(* Logix 5000 project; controller R21 vendor 1 type 14 code 96 rev 21.11; software revision 21.00 *)

TASK DNP3ReportByException (periodic, rate 20 ms, priority 10, watchdog 500 ms) : DNP3Events
TASK MainTask (continuous, watchdog 500 ms) : MainProgram

MODULES
   Local : vendor 1 type 14 code 96 (ICP 0, rev 21.11)
      eth : vendor 1 type 12 code 200 (Ethernet 192.168.1.129, ICP 1, rev 5.7)
         DNPM01 : vendor 309 type 12 code 5212 (Ethernet 192.168.1.161, rev 1.3, StandardDataDriven RPI 500 ms)
END_MODULES

TYPE PLX51DNPInput :
STRUCT
   Instance : STRING;
   Status : PLX51DNPStatus;
   MasterMappedStatus : BOOL[1024];
   TransactionRate : DINT;
   Temperature : REAL;
   DNP3RxPacketCount : DINT;
   DNP3TxPacketCount : DINT;
   DNP3ChecksumErrors : DINT;
   DNP3MsgTimeout : DINT;
   AuthenticationFailures : DINT;
   SessionKeyChanges : DINT;
   TagReads : DINT;
   TagWrites : DINT;
   TagConnectionFailures : DINT;
   TagErrors : DINT;
   MasterEventBufferIndex : DINT;
END_STRUCT
END_TYPE

TYPE PLX51DNPOutput :
STRUCT
   RoutingInhibited : BOOL;
END_STRUCT
END_TYPE

TYPE PLX51DNPStatus :
STRUCT
   ReactiveTagMode : BOOL;
   ScheduledTagMode : BOOL;
   UnscheduledMode : BOOL;
   ConfigurationValid : BOOL;
   RoutingInhibited : BOOL;
   DNP3EventLogOk : BOOL;
   DNP3EventLogOverflow : BOOL;
END_STRUCT
END_TYPE

TYPE PSDNP3AnalogInput16Flag :
STRUCT
   Online : BOOL;
   Restart : BOOL;
   CommLost : BOOL;
   RemoteForced : BOOL;
   LocalForced : BOOL;
   OverRange : BOOL;
   ReferenceError : BOOL;
   Value : INT;
END_STRUCT
END_TYPE

TYPE PSDNP3AnalogInput32Flag :
STRUCT
   Online : BOOL;
   Restart : BOOL;
   CommLost : BOOL;
   RemoteForced : BOOL;
   LocalForced : BOOL;
   OverRange : BOOL;
   ReferenceError : BOOL;
   Value : DINT;
END_STRUCT
END_TYPE

TYPE PSDNP3AnalogInputRealFlag :
STRUCT
   Online : BOOL;
   Restart : BOOL;
   CommLost : BOOL;
   RemoteForced : BOOL;
   LocalForced : BOOL;
   OverRange : BOOL;
   ReferenceError : BOOL;
   Value : REAL;
END_STRUCT
END_TYPE

TYPE PSDNP3AnalogInputVar0 :
STRUCT
   Online : BOOL;
   Restart : BOOL;
   CommLost : BOOL;
   RemoteForced : BOOL;
   LocalForced : BOOL;
   OverRange : BOOL;
   ReferenceError : BOOL;
   IntValue : DINT;
   FloatValue : REAL;
END_STRUCT
END_TYPE

TYPE PSDNP3AnalogOutput16 :
STRUCT
   RequestPending : BOOL;
   Reserved : INT;
   Value : INT;
   Status : SINT;
END_STRUCT
END_TYPE

TYPE PSDNP3AnalogOutput32 :
STRUCT
   RequestPending : BOOL;
   Reserved : INT;
   Value : DINT;
   Status : SINT;
END_STRUCT
END_TYPE

TYPE PSDNP3AnalogOutputReal :
STRUCT
   RequestPending : BOOL;
   Reserved : INT;
   Value : REAL;
   Status : SINT;
END_STRUCT
END_TYPE

TYPE PSDNP3AnalogOutputStatus16Flag :
STRUCT
   Online : BOOL;
   Restart : BOOL;
   CommLost : BOOL;
   RemoteForced : BOOL;
   LocalForced : BOOL;
   OverRange : BOOL;
   ReferenceError : BOOL;
   Value : INT;
END_STRUCT
END_TYPE

TYPE PSDNP3AnalogOutputStatus32Flag :
STRUCT
   Online : BOOL;
   Restart : BOOL;
   CommLost : BOOL;
   RemoteForced : BOOL;
   LocalForced : BOOL;
   OverRange : BOOL;
   ReferenceError : BOOL;
   Value : DINT;
END_STRUCT
END_TYPE

TYPE PSDNP3AnalogOutputStatusRealFlag :
STRUCT
   Online : BOOL;
   Restart : BOOL;
   CommLost : BOOL;
   RemoteForced : BOOL;
   LocalForced : BOOL;
   OverRange : BOOL;
   ReferenceError : BOOL;
   Value : REAL;
END_STRUCT
END_TYPE

TYPE PSDNP3AnalogOutputVar0 :
STRUCT
   Online : BOOL;
   Restart : BOOL;
   CommLost : BOOL;
   RemoteForced : BOOL;
   LocalForced : BOOL;
   OverRange : BOOL;
   ReferenceError : BOOL;
   IntValue : DINT;
   FloatValue : REAL;
END_STRUCT
END_TYPE

TYPE PSDNP3BinaryInputPacked :
STRUCT
   BinaryValues : SINT[32];
END_STRUCT
END_TYPE

TYPE PSDNP3BinaryInputWithFlag :
STRUCT
   Online : BOOL;
   Restart : BOOL;
   CommLost : BOOL;
   RemoteForced : BOOL;
   LocalForced : BOOL;
   ChatterFilter : BOOL;
   Reserved : BOOL;
   State : BOOL;
END_STRUCT
END_TYPE

TYPE PSDNP3BinaryOutputPacked :
STRUCT
   BinaryValues : SINT[32];
END_STRUCT
END_TYPE

TYPE PSDNP3BinaryOutputPulse :
STRUCT
   Count : SINT;
   OnTimer : TIMER;
   OffTimer : TIMER;
END_STRUCT
END_TYPE

TYPE PSDNP3BinaryOutputWithFlag :
STRUCT
   Online : BOOL;
   Restart : BOOL;
   CommLost : BOOL;
   RemoteForced : BOOL;
   LocalForced : BOOL;
   Reserved1 : BOOL;
   Reserved2 : BOOL;
   State : BOOL;
END_STRUCT
END_TYPE

TYPE PSDNP3Counter16WithFlag :
STRUCT
   Online : BOOL;
   Restart : BOOL;
   CommLost : BOOL;
   RemoteForced : BOOL;
   LocalForced : BOOL;
   RollOver : BOOL;
   Discontinuity : BOOL;
   Value : INT;
END_STRUCT
END_TYPE

TYPE PSDNP3Counter32WithFlag :
STRUCT
   Online : BOOL;
   Restart : BOOL;
   CommLost : BOOL;
   RemoteForced : BOOL;
   LocalForced : BOOL;
   RollOver : BOOL;
   Discontinuity : BOOL;
   Value : DINT;
END_STRUCT
END_TYPE

TYPE PSDNP3CROB :
STRUCT
   RequestPending : BOOL;
   Reserved : INT;
   ControlCode : SINT;
   Count : SINT;
   OnTime : DINT;
   OffTime : DINT;
   StatusCode : SINT;
END_STRUCT
END_TYPE

TYPE PSDNP3DoubleBinaryInputPacked :
STRUCT
   BinaryValues : SINT[32];
END_STRUCT
END_TYPE

TYPE PSDNP3DoubleBinaryInputWithFlag :
STRUCT
   Online : BOOL;
   Restart : BOOL;
   CommLost : BOOL;
   RemoteForced : BOOL;
   LocalForced : BOOL;
   ChatterFilter : BOOL;
   State0 : BOOL;
   State1 : BOOL;
END_STRUCT
END_TYPE

TYPE PSDNP3FreezeCmd :
STRUCT
   RequestPending : BOOL;
END_STRUCT
END_TYPE

TYPE PSDNP3FrozenAnalog16WithFlag :
STRUCT
   Online : BOOL;
   Restart : BOOL;
   CommLost : BOOL;
   RemoteForced : BOOL;
   LocalForced : BOOL;
   OverRange : BOOL;
   ReferenceErr : BOOL;
   Value : INT;
END_STRUCT
END_TYPE

TYPE PSDNP3FrozenAnalog16WithFlagTime :
STRUCT
   Online : BOOL;
   Restart : BOOL;
   CommLost : BOOL;
   RemoteForced : BOOL;
   LocalForced : BOOL;
   OverRange : BOOL;
   ReferenceErr : BOOL;
   Value : INT;
   Reserved : DINT;
   TimeOfOccurrence : LINT;
END_STRUCT
END_TYPE

TYPE PSDNP3FrozenAnalog32WithFlag :
STRUCT
   Online : BOOL;
   Restart : BOOL;
   CommLost : BOOL;
   RemoteForced : BOOL;
   LocalForced : BOOL;
   OverRange : BOOL;
   ReferenceErr : BOOL;
   Value : DINT;
END_STRUCT
END_TYPE

TYPE PSDNP3FrozenAnalog32WithFlagTime :
STRUCT
   Online : BOOL;
   Restart : BOOL;
   CommLost : BOOL;
   RemoteForced : BOOL;
   LocalForced : BOOL;
   OverRange : BOOL;
   ReferenceErr : BOOL;
   Value : DINT;
   TimeOfOccurrence : LINT;
END_STRUCT
END_TYPE

TYPE PSDNP3FrozenAnalogRealWithFlag :
STRUCT
   Online : BOOL;
   Restart : BOOL;
   CommLost : BOOL;
   RemoteForced : BOOL;
   LocalForced : BOOL;
   OverRange : BOOL;
   ReferenceErr : BOOL;
   Value : REAL;
END_STRUCT
END_TYPE

TYPE PSDNP3FrozenCounter16WithFlag :
STRUCT
   Online : BOOL;
   Restart : BOOL;
   CommLost : BOOL;
   RemoteForced : BOOL;
   LocalForced : BOOL;
   RollOver : BOOL;
   Discontinuity : BOOL;
   Value : INT;
END_STRUCT
END_TYPE

TYPE PSDNP3FrozenCounter16WithFlagTime :
STRUCT
   Online : BOOL;
   Restart : BOOL;
   CommLost : BOOL;
   RemoteForced : BOOL;
   LocalForced : BOOL;
   RollOver : BOOL;
   Discontinuity : BOOL;
   Value : INT;
   TimeOfOccurrence : LINT;
END_STRUCT
END_TYPE

TYPE PSDNP3FrozenCounter32WithFlag :
STRUCT
   Online : BOOL;
   Restart : BOOL;
   CommLost : BOOL;
   RemoteForced : BOOL;
   LocalForced : BOOL;
   RollOver : BOOL;
   Discontinuity : BOOL;
   Value : DINT;
END_STRUCT
END_TYPE

TYPE PSDNP3FrozenCounter32WithFlagTime :
STRUCT
   Online : BOOL;
   Restart : BOOL;
   CommLost : BOOL;
   RemoteForced : BOOL;
   LocalForced : BOOL;
   RollOver : BOOL;
   Discontinuity : BOOL;
   Value : DINT;
   TimeOfOccurrence : LINT;
END_STRUCT
END_TYPE

TYPE PSDNP3MasterEvent :
STRUCT
   EvtPending : DINT;
   EvtGroup : SINT;
   EvtFlags : SINT;
   EvtSrcNodeAddress : INT;
   EvtSrcIPAddress : INT[4];
   EvtElementIndex : DINT;
   Reserved : DINT;
   EvtTimeStamp : LINT;
   EvtFloatValue : REAL;
   EvtIntegerValue : DINT;
END_STRUCT
END_TYPE

TYPE PSDNP3MsgRequest :
STRUCT
   DestinationNode : INT;
   RequestDataSize : INT;
   IPAddress : INT[4];
   Function : DINT;
   RequestData : SINT[255];
END_STRUCT
END_TYPE

TYPE PSDNP3MsgResponse :
STRUCT
   DNP3Indicators : INT;
   ResponseDataSize : INT;
   ResponseData : SINT[255];
END_STRUCT
END_TYPE

ADD_ON_INSTRUCTION PSDNP3EventG01V02   (* revision 1.0, vendor ProSoft Technology Inc *)
VAR_IN_OUT
   EventBuffer : PSDNP3MasterEvent[1]; {required}
END_VAR
VAR_INPUT
   BufferSize : DINT; {required}
   CurrentBufferIndex : DINT; {required}
   Reset : BOOL; {required}
   OutstationNodeAddress : INT; {required}
   OutstationIPAddress0 : INT; {required}
   OutstationIPAddress1 : INT; {required}
   OutstationIPAddress2 : INT; {required}
   OutstationIPAddress3 : INT; {required}
END_VAR
VAR_IN_OUT
   DNP3StaticObject : PSDNP3BinaryInputWithFlag[1]; {required}
END_VAR
VAR_INPUT
   MaxtElementCount : DINT; {required}
END_VAR
VAR_OUTPUT
   EventsProcessed : DINT; {access Read Only, visible}
   LastElementIndex : DINT; {access Read Only, visible}
   LastValue : BOOL; {access Read Only, visible}
   LastStatus : SINT; {access Read Only, visible}
   CurrentUnloadIndex : DINT; {access Read Only, visible}
END_VAR
VAR
   UnloadIndex : DINT; {access None}
   EnableInTemp : BOOL; {access None}
   InitialScan : BOOL; {access None}
   EntryValidForProcessing : BOOL; {access None}
   ElementIndex : DINT; {access None}
   NextIndex : DINT; {access None}
   ResetPulse : BOOL; {access None}
   ResetONS : BOOL; {access None}
END_VAR

ROUTINE Logic   (* ladder *)
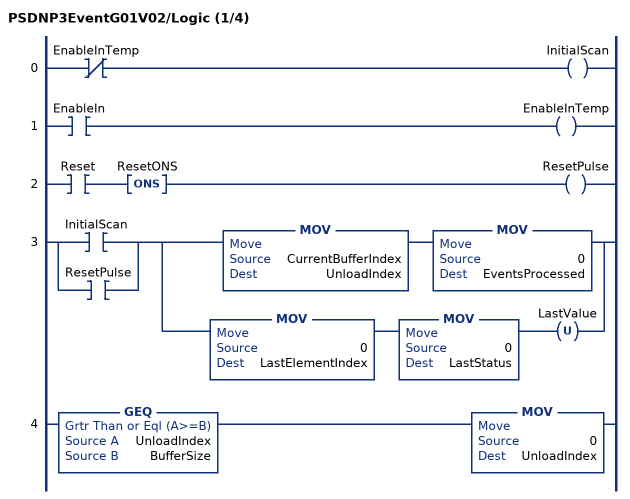
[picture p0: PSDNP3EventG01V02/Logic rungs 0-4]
   0: XIO(EnableInTemp)OTE(InitialScan);
   1: XIC(EnableIn)OTE(EnableInTemp);
   2: XIC(Reset)ONS(ResetONS)OTE(ResetPulse);
   3: [XIC(InitialScan) ,XIC(ResetPulse) ][MOV(CurrentBufferIndex,UnloadIndex) MOV(0,EventsProcessed) ,MOV(0,LastElementIndex) MOV(0,LastStatus) OTU(LastValue) ];
   4: GEQ(UnloadIndex,BufferSize)MOV(0,UnloadIndex);
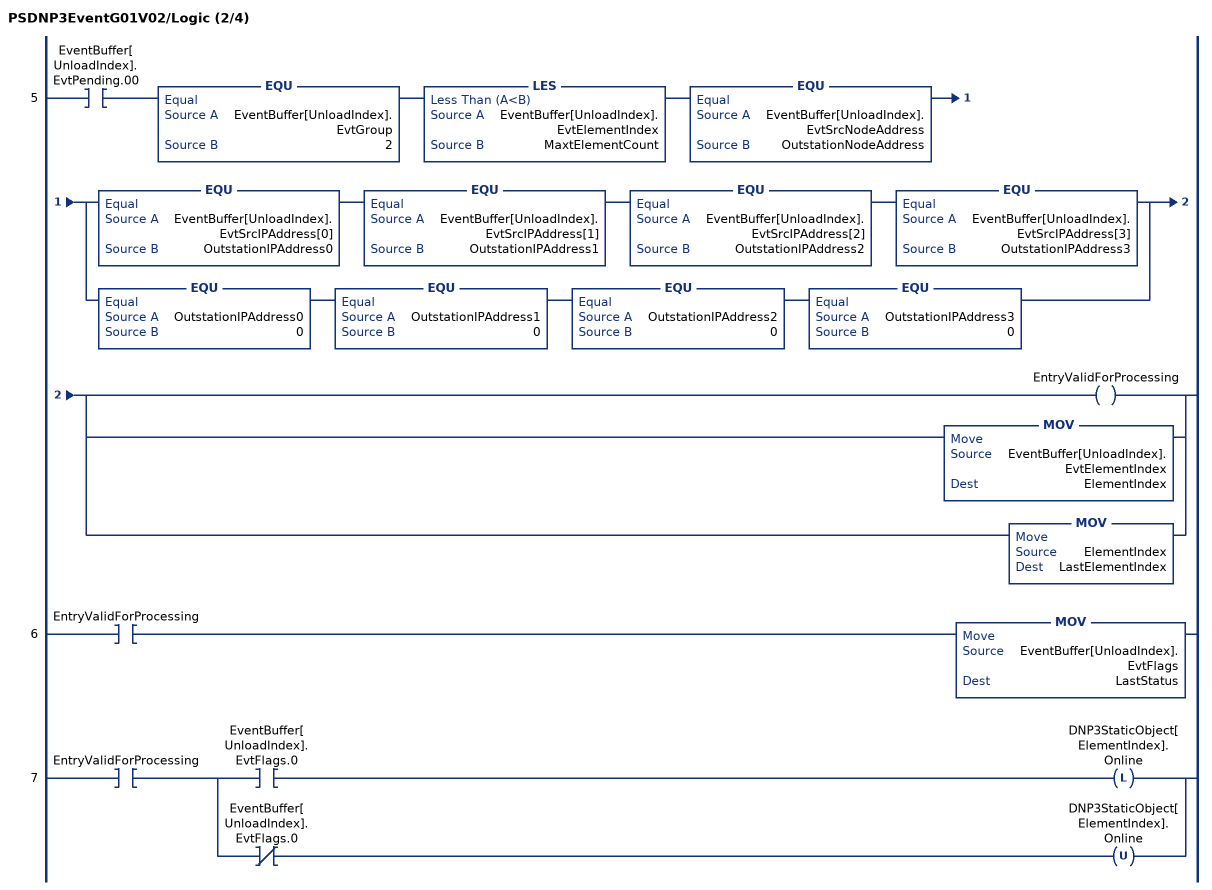
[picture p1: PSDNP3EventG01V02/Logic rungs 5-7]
   5: XIC(EventBuffer[UnloadIndex].EvtPending.00)EQU(EventBuffer[UnloadIndex].EvtGroup,2)LES(EventBuffer[UnloadIndex].EvtElementIndex,MaxtElementCount)EQU(EventBuffer[UnloadIndex].EvtSrcNodeAddress,OutstationNodeAddress)[EQU(EventBuffer[UnloadIndex].EvtSrcIPAddress[0],OutstationIPAddress0) EQU(EventBuffer[UnloadIndex].EvtSrcIPAddress[1],OutstationIPAddress1) EQU(EventBuffer[UnloadIndex].EvtSrcIPAddress[2],OutstationIPAddress2) EQU(EventBuffer[UnloadIndex].EvtSrcIPAddress[3],OutstationIPAddress3) ,EQU(OutstationIPAddress0,0) EQU(OutstationIPAddress1,0) EQU(OutstationIPAddress2,0) EQU(OutstationIPAddress3,0) ][OTE(EntryValidForProcessing) ,MOV(EventBuffer[UnloadIndex].EvtElementIndex,ElementIndex) ,MOV(ElementIndex,LastElementIndex) ];
   6: XIC(EntryValidForProcessing)MOV(EventBuffer[UnloadIndex].EvtFlags,LastStatus);
   7: XIC(EntryValidForProcessing)[XIC(EventBuffer[UnloadIndex].EvtFlags.0) OTL(DNP3StaticObject[ElementIndex].Online) ,XIO(EventBuffer[UnloadIndex].EvtFlags.0) OTU(DNP3StaticObject[ElementIndex].Online) ];
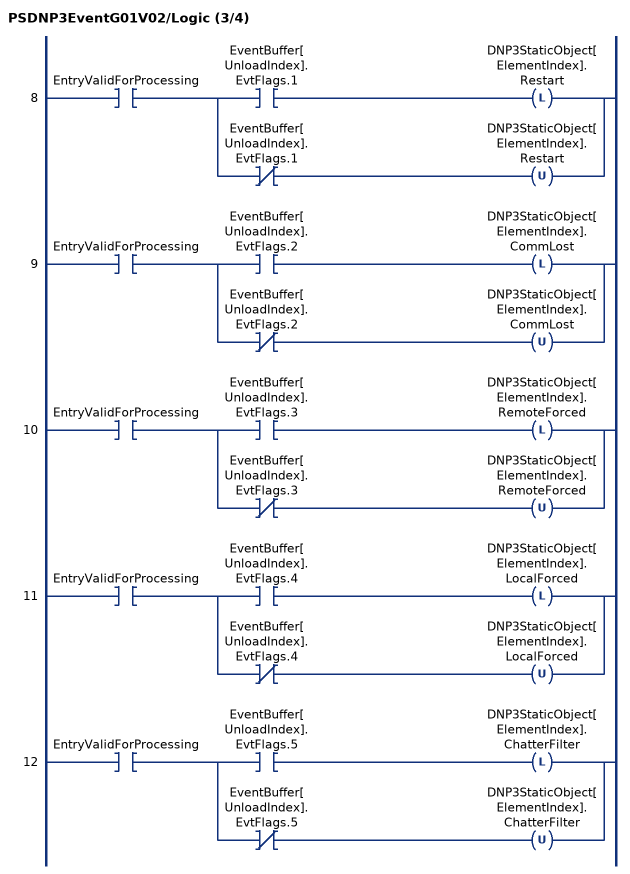
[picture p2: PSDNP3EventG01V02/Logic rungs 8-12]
   8: XIC(EntryValidForProcessing)[XIC(EventBuffer[UnloadIndex].EvtFlags.1) OTL(DNP3StaticObject[ElementIndex].Restart) ,XIO(EventBuffer[UnloadIndex].EvtFlags.1) OTU(DNP3StaticObject[ElementIndex].Restart) ];
   9: XIC(EntryValidForProcessing)[XIC(EventBuffer[UnloadIndex].EvtFlags.2) OTL(DNP3StaticObject[ElementIndex].CommLost) ,XIO(EventBuffer[UnloadIndex].EvtFlags.2) OTU(DNP3StaticObject[ElementIndex].CommLost) ];
   10: XIC(EntryValidForProcessing)[XIC(EventBuffer[UnloadIndex].EvtFlags.3) OTL(DNP3StaticObject[ElementIndex].RemoteForced) ,XIO(EventBuffer[UnloadIndex].EvtFlags.3) OTU(DNP3StaticObject[ElementIndex].RemoteForced) ];
   11: XIC(EntryValidForProcessing)[XIC(EventBuffer[UnloadIndex].EvtFlags.4) OTL(DNP3StaticObject[ElementIndex].LocalForced) ,XIO(EventBuffer[UnloadIndex].EvtFlags.4) OTU(DNP3StaticObject[ElementIndex].LocalForced) ];
   12: XIC(EntryValidForProcessing)[XIC(EventBuffer[UnloadIndex].EvtFlags.5) OTL(DNP3StaticObject[ElementIndex].ChatterFilter) ,XIO(EventBuffer[UnloadIndex].EvtFlags.5) OTU(DNP3StaticObject[ElementIndex].ChatterFilter) ];
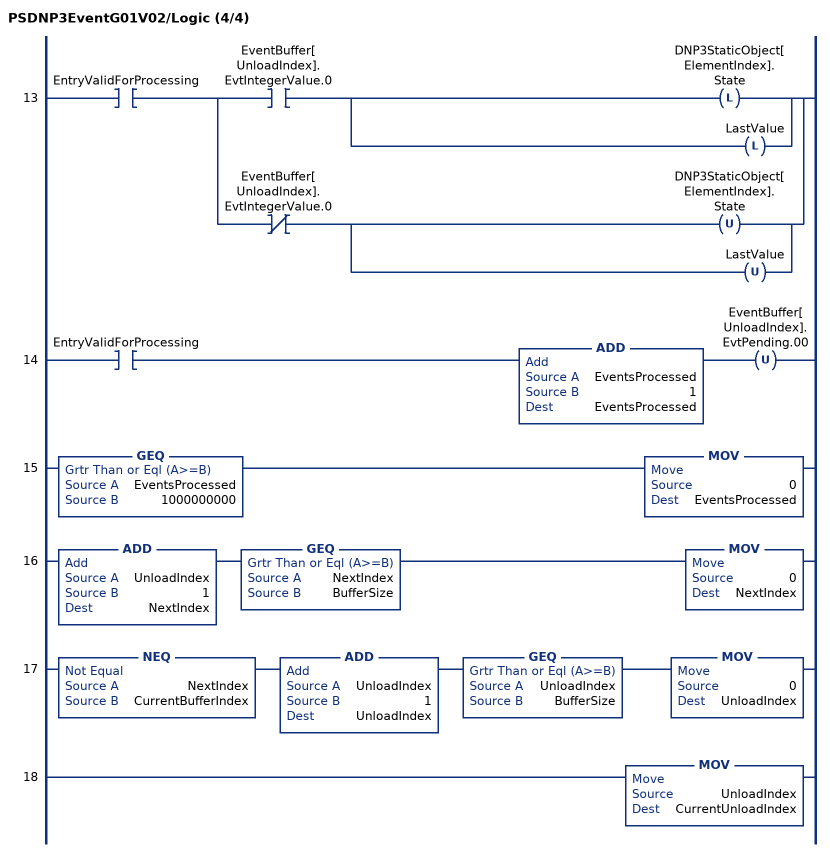
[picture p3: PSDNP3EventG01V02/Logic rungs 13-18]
   13: XIC(EntryValidForProcessing)[XIC(EventBuffer[UnloadIndex].EvtIntegerValue.0) [OTL(DNP3StaticObject[ElementIndex].State) ,OTL(LastValue) ] ,XIO(EventBuffer[UnloadIndex].EvtIntegerValue.0) [OTU(DNP3StaticObject[ElementIndex].State) ,OTU(LastValue) ] ];
   14: XIC(EntryValidForProcessing)ADD(EventsProcessed,1,EventsProcessed)OTU(EventBuffer[UnloadIndex].EvtPending.00);
   15: GEQ(EventsProcessed,1000000000)MOV(0,EventsProcessed);
   16: ADD(UnloadIndex,1,NextIndex)GEQ(NextIndex,BufferSize)MOV(0,NextIndex);
   17: NEQ(NextIndex,CurrentBufferIndex)ADD(UnloadIndex,1,UnloadIndex)GEQ(UnloadIndex,BufferSize)MOV(0,UnloadIndex);
   18: MOV(UnloadIndex,CurrentUnloadIndex);
END_ROUTINE
END_ADD_ON_INSTRUCTION

ADD_ON_INSTRUCTION PSDNP3EventG03V02   (* revision 1.0, vendor ProSoft Technology Inc *)
VAR_IN_OUT
   EventBuffer : PSDNP3MasterEvent[1]; {required}
END_VAR
VAR_INPUT
   BufferSize : DINT; {required}
   CurrentBufferIndex : DINT; {required}
   Reset : BOOL; {required}
   OutstationNodeAddress : INT; {required}
   OutstationIPAddress0 : INT; {required}
   OutstationIPAddress1 : INT; {required}
   OutstationIPAddress2 : INT; {required}
   OutstationIPAddress3 : INT; {required}
END_VAR
VAR_IN_OUT
   DNP3StaticObject : PSDNP3DoubleBinaryInputWithFlag[1]; {required}
END_VAR
VAR_INPUT
   MaxtElementCount : DINT; {required}
END_VAR
VAR_OUTPUT
   EventsProcessed : DINT; {access Read Only, visible}
   LastElementIndex : DINT; {access Read Only, visible}
   LastValue : SINT; {access Read Only, visible}
   LastStatus : SINT; {access Read Only, visible}
   CurrentUnloadIndex : DINT; {access Read Only, visible}
END_VAR
VAR
   UnloadIndex : DINT; {access None}
   EnableInTemp : BOOL; {access None}
   InitialScan : BOOL; {access None}
   EntryValidForProcessing : BOOL; {access None}
   ElementIndex : DINT; {access None}
   NextIndex : DINT; {access None}
   ResetPulse : BOOL; {access None}
   ResetONS : BOOL; {access None}
END_VAR

ROUTINE Logic   (* ladder *)
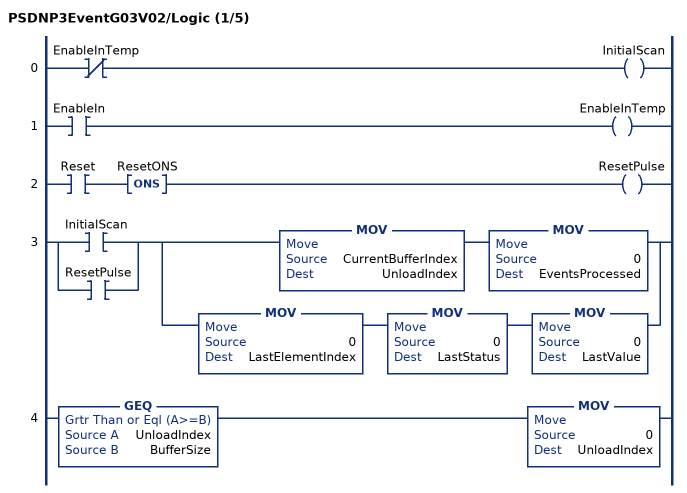
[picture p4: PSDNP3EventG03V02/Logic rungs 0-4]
   0: XIO(EnableInTemp)OTE(InitialScan);
   1: XIC(EnableIn)OTE(EnableInTemp);
   2: XIC(Reset)ONS(ResetONS)OTE(ResetPulse);
   3: [XIC(InitialScan) ,XIC(ResetPulse) ][MOV(CurrentBufferIndex,UnloadIndex) MOV(0,EventsProcessed) ,MOV(0,LastElementIndex) MOV(0,LastStatus) MOV(0,LastValue) ];
   4: GEQ(UnloadIndex,BufferSize)MOV(0,UnloadIndex);
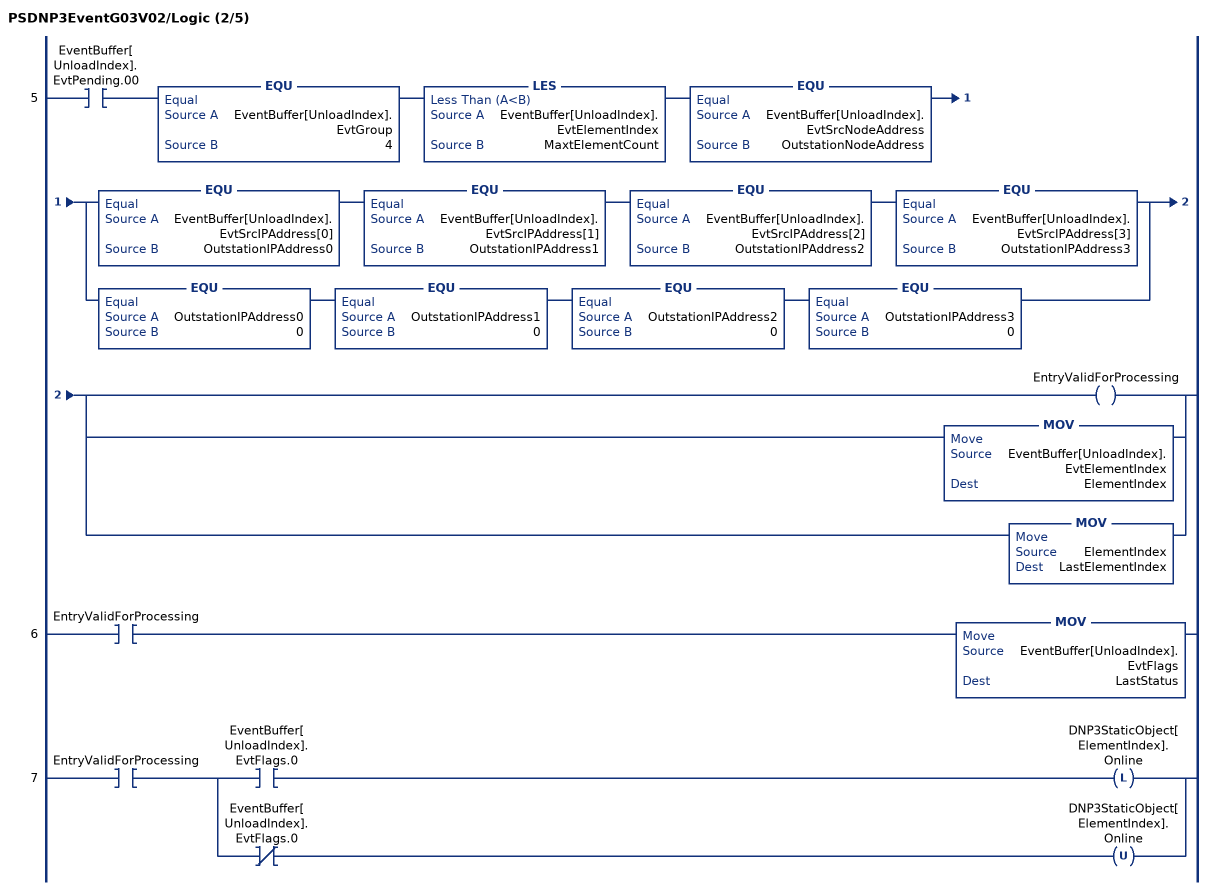
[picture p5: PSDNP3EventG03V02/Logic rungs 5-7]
   5: XIC(EventBuffer[UnloadIndex].EvtPending.00)EQU(EventBuffer[UnloadIndex].EvtGroup,4)LES(EventBuffer[UnloadIndex].EvtElementIndex,MaxtElementCount)EQU(EventBuffer[UnloadIndex].EvtSrcNodeAddress,OutstationNodeAddress)[EQU(EventBuffer[UnloadIndex].EvtSrcIPAddress[0],OutstationIPAddress0) EQU(EventBuffer[UnloadIndex].EvtSrcIPAddress[1],OutstationIPAddress1) EQU(EventBuffer[UnloadIndex].EvtSrcIPAddress[2],OutstationIPAddress2) EQU(EventBuffer[UnloadIndex].EvtSrcIPAddress[3],OutstationIPAddress3) ,EQU(OutstationIPAddress0,0) EQU(OutstationIPAddress1,0) EQU(OutstationIPAddress2,0) EQU(OutstationIPAddress3,0) ][OTE(EntryValidForProcessing) ,MOV(EventBuffer[UnloadIndex].EvtElementIndex,ElementIndex) ,MOV(ElementIndex,LastElementIndex) ];
   6: XIC(EntryValidForProcessing)MOV(EventBuffer[UnloadIndex].EvtFlags,LastStatus);
   7: XIC(EntryValidForProcessing)[XIC(EventBuffer[UnloadIndex].EvtFlags.0) OTL(DNP3StaticObject[ElementIndex].Online) ,XIO(EventBuffer[UnloadIndex].EvtFlags.0) OTU(DNP3StaticObject[ElementIndex].Online) ];
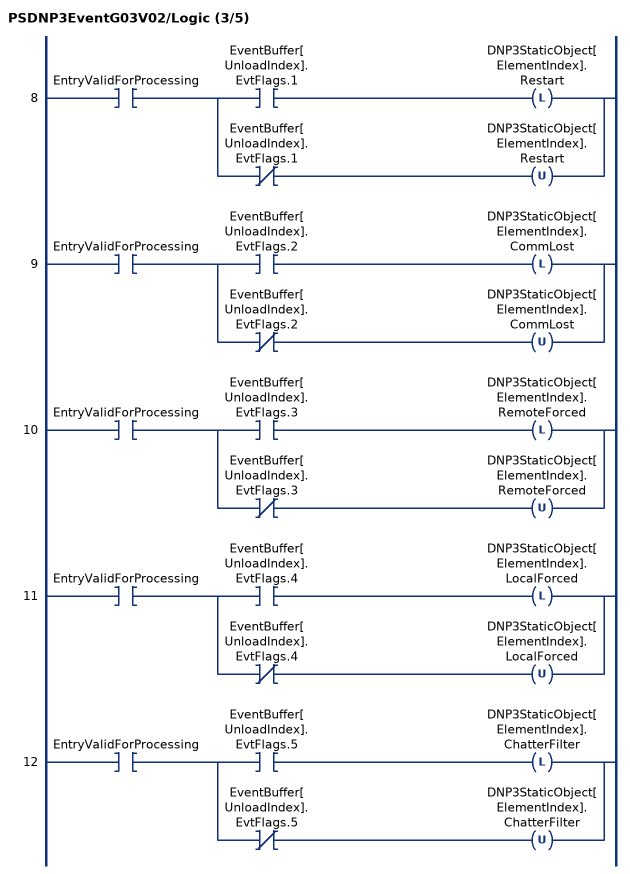
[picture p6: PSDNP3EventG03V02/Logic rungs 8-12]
   8: XIC(EntryValidForProcessing)[XIC(EventBuffer[UnloadIndex].EvtFlags.1) OTL(DNP3StaticObject[ElementIndex].Restart) ,XIO(EventBuffer[UnloadIndex].EvtFlags.1) OTU(DNP3StaticObject[ElementIndex].Restart) ];
   9: XIC(EntryValidForProcessing)[XIC(EventBuffer[UnloadIndex].EvtFlags.2) OTL(DNP3StaticObject[ElementIndex].CommLost) ,XIO(EventBuffer[UnloadIndex].EvtFlags.2) OTU(DNP3StaticObject[ElementIndex].CommLost) ];
   10: XIC(EntryValidForProcessing)[XIC(EventBuffer[UnloadIndex].EvtFlags.3) OTL(DNP3StaticObject[ElementIndex].RemoteForced) ,XIO(EventBuffer[UnloadIndex].EvtFlags.3) OTU(DNP3StaticObject[ElementIndex].RemoteForced) ];
   11: XIC(EntryValidForProcessing)[XIC(EventBuffer[UnloadIndex].EvtFlags.4) OTL(DNP3StaticObject[ElementIndex].LocalForced) ,XIO(EventBuffer[UnloadIndex].EvtFlags.4) OTU(DNP3StaticObject[ElementIndex].LocalForced) ];
   12: XIC(EntryValidForProcessing)[XIC(EventBuffer[UnloadIndex].EvtFlags.5) OTL(DNP3StaticObject[ElementIndex].ChatterFilter) ,XIO(EventBuffer[UnloadIndex].EvtFlags.5) OTU(DNP3StaticObject[ElementIndex].ChatterFilter) ];
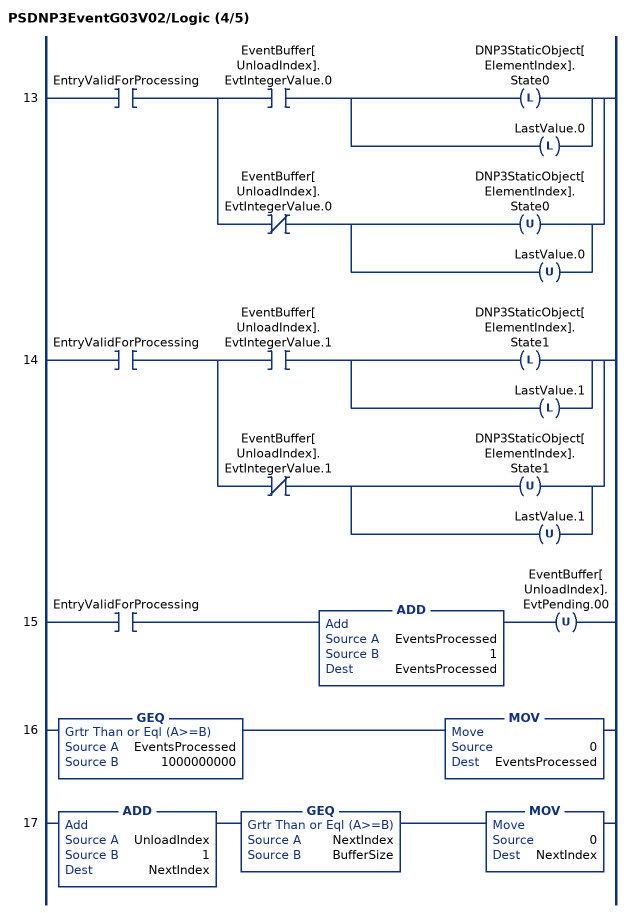
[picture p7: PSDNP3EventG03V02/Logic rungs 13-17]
   13: XIC(EntryValidForProcessing)[XIC(EventBuffer[UnloadIndex].EvtIntegerValue.0) [OTL(DNP3StaticObject[ElementIndex].State0) ,OTL(LastValue.0) ] ,XIO(EventBuffer[UnloadIndex].EvtIntegerValue.0) [OTU(DNP3StaticObject[ElementIndex].State0) ,OTU(LastValue.0) ] ];
   14: XIC(EntryValidForProcessing)[XIC(EventBuffer[UnloadIndex].EvtIntegerValue.1) [OTL(DNP3StaticObject[ElementIndex].State1) ,OTL(LastValue.1) ] ,XIO(EventBuffer[UnloadIndex].EvtIntegerValue.1) [OTU(DNP3StaticObject[ElementIndex].State1) ,OTU(LastValue.1) ] ];
   15: XIC(EntryValidForProcessing)ADD(EventsProcessed,1,EventsProcessed)OTU(EventBuffer[UnloadIndex].EvtPending.00);
   16: GEQ(EventsProcessed,1000000000)MOV(0,EventsProcessed);
   17: ADD(UnloadIndex,1,NextIndex)GEQ(NextIndex,BufferSize)MOV(0,NextIndex);
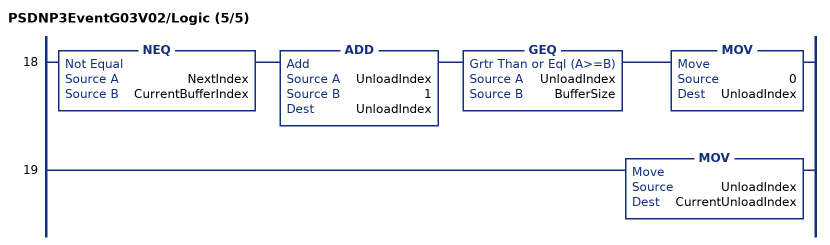
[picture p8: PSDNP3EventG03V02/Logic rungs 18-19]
   18: NEQ(NextIndex,CurrentBufferIndex)ADD(UnloadIndex,1,UnloadIndex)GEQ(UnloadIndex,BufferSize)MOV(0,UnloadIndex);
   19: MOV(UnloadIndex,CurrentUnloadIndex);
END_ROUTINE
END_ADD_ON_INSTRUCTION

ADD_ON_INSTRUCTION PSDNP3EventG10V02   (* revision 1.0, vendor ProSoft Technology Inc *)
VAR_IN_OUT
   EventBuffer : PSDNP3MasterEvent[1]; {required}
END_VAR
VAR_INPUT
   BufferSize : DINT; {required}
   CurrentBufferIndex : DINT; {required}
   Reset : BOOL; {required}
   OutstationNodeAddress : INT; {required}
   OutstationIPAddress0 : INT; {required}
   OutstationIPAddress1 : INT; {required}
   OutstationIPAddress2 : INT; {required}
   OutstationIPAddress3 : INT; {required}
END_VAR
VAR_IN_OUT
   DNP3StaticObject : PSDNP3BinaryOutputWithFlag[1]; {required}
END_VAR
VAR_INPUT
   MaxtElementCount : DINT; {required}
END_VAR
VAR_OUTPUT
   EventsProcessed : DINT; {access Read Only, visible}
   LastElementIndex : DINT; {access Read Only, visible}
   LastValue : BOOL; {access Read Only, visible}
   LastStatus : SINT; {access Read Only, visible}
   CurrentUnloadIndex : DINT; {access Read Only, visible}
END_VAR
VAR
   UnloadIndex : DINT; {access None}
   EnableInTemp : BOOL; {access None}
   InitialScan : BOOL; {access None}
   EntryValidForProcessing : BOOL; {access None}
   ElementIndex : DINT; {access None}
   NextIndex : DINT; {access None}
   ResetPulse : BOOL; {access None}
   ResetONS : BOOL; {access None}
END_VAR

ROUTINE Logic   (* ladder *)
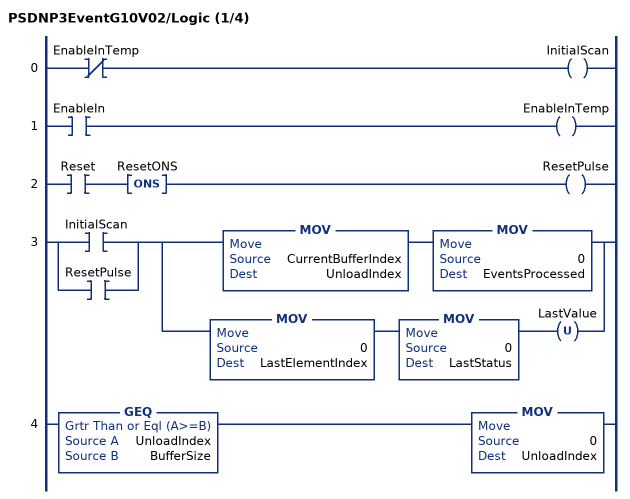
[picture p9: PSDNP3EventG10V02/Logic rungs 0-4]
   0: XIO(EnableInTemp)OTE(InitialScan);
   1: XIC(EnableIn)OTE(EnableInTemp);
   2: XIC(Reset)ONS(ResetONS)OTE(ResetPulse);
   3: [XIC(InitialScan) ,XIC(ResetPulse) ][MOV(CurrentBufferIndex,UnloadIndex) MOV(0,EventsProcessed) ,MOV(0,LastElementIndex) MOV(0,LastStatus) OTU(LastValue) ];
   4: GEQ(UnloadIndex,BufferSize)MOV(0,UnloadIndex);
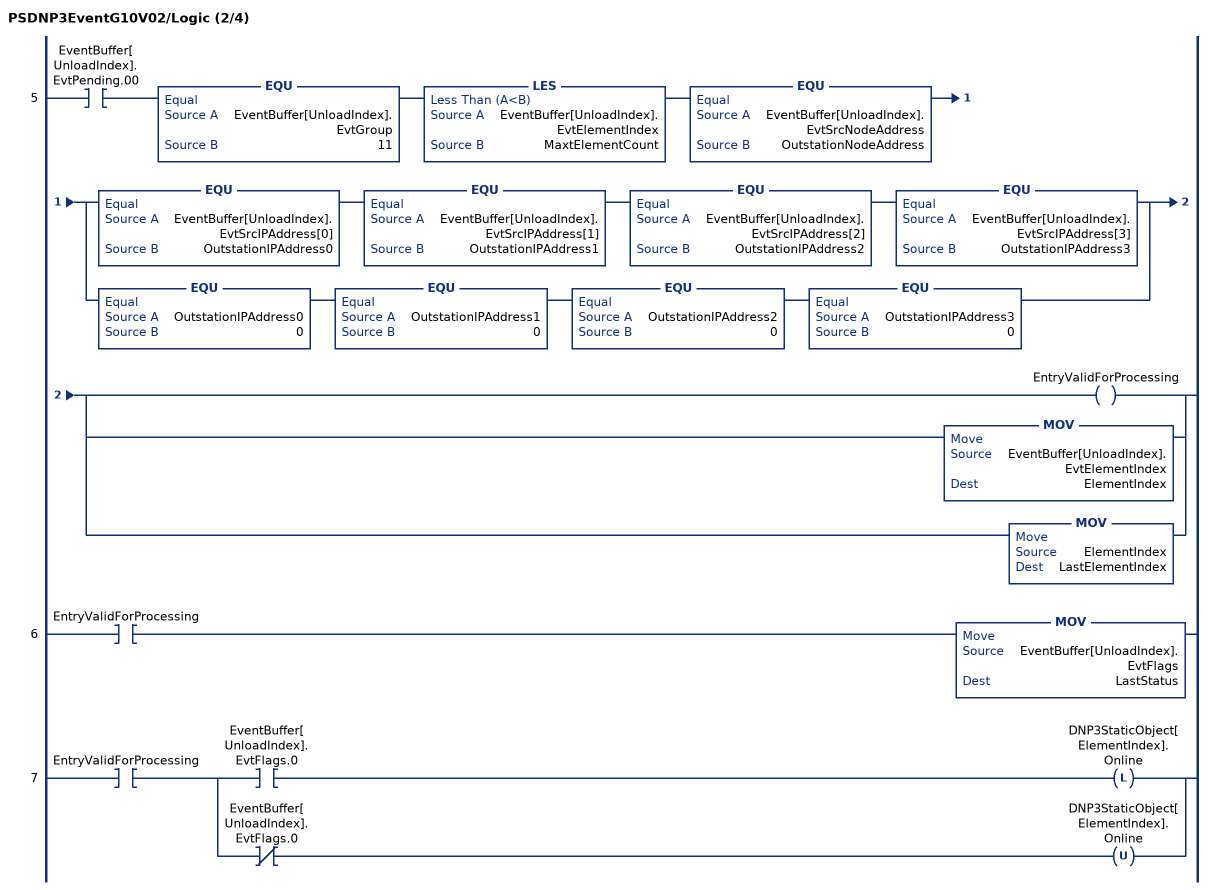
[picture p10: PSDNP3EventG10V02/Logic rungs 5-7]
   5: XIC(EventBuffer[UnloadIndex].EvtPending.00)EQU(EventBuffer[UnloadIndex].EvtGroup,11)LES(EventBuffer[UnloadIndex].EvtElementIndex,MaxtElementCount)EQU(EventBuffer[UnloadIndex].EvtSrcNodeAddress,OutstationNodeAddress)[EQU(EventBuffer[UnloadIndex].EvtSrcIPAddress[0],OutstationIPAddress0) EQU(EventBuffer[UnloadIndex].EvtSrcIPAddress[1],OutstationIPAddress1) EQU(EventBuffer[UnloadIndex].EvtSrcIPAddress[2],OutstationIPAddress2) EQU(EventBuffer[UnloadIndex].EvtSrcIPAddress[3],OutstationIPAddress3) ,EQU(OutstationIPAddress0,0) EQU(OutstationIPAddress1,0) EQU(OutstationIPAddress2,0) EQU(OutstationIPAddress3,0) ][OTE(EntryValidForProcessing) ,MOV(EventBuffer[UnloadIndex].EvtElementIndex,ElementIndex) ,MOV(ElementIndex,LastElementIndex) ];
   6: XIC(EntryValidForProcessing)MOV(EventBuffer[UnloadIndex].EvtFlags,LastStatus);
   7: XIC(EntryValidForProcessing)[XIC(EventBuffer[UnloadIndex].EvtFlags.0) OTL(DNP3StaticObject[ElementIndex].Online) ,XIO(EventBuffer[UnloadIndex].EvtFlags.0) OTU(DNP3StaticObject[ElementIndex].Online) ];
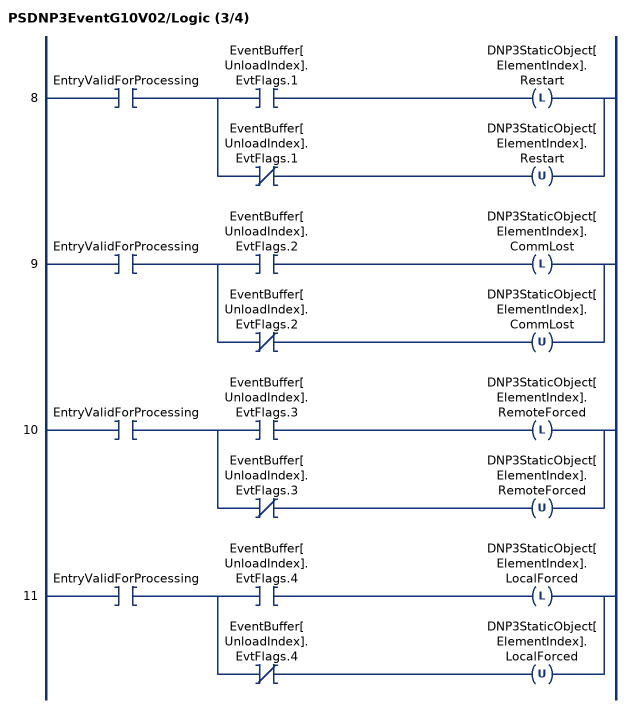
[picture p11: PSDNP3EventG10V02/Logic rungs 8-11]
   8: XIC(EntryValidForProcessing)[XIC(EventBuffer[UnloadIndex].EvtFlags.1) OTL(DNP3StaticObject[ElementIndex].Restart) ,XIO(EventBuffer[UnloadIndex].EvtFlags.1) OTU(DNP3StaticObject[ElementIndex].Restart) ];
   9: XIC(EntryValidForProcessing)[XIC(EventBuffer[UnloadIndex].EvtFlags.2) OTL(DNP3StaticObject[ElementIndex].CommLost) ,XIO(EventBuffer[UnloadIndex].EvtFlags.2) OTU(DNP3StaticObject[ElementIndex].CommLost) ];
   10: XIC(EntryValidForProcessing)[XIC(EventBuffer[UnloadIndex].EvtFlags.3) OTL(DNP3StaticObject[ElementIndex].RemoteForced) ,XIO(EventBuffer[UnloadIndex].EvtFlags.3) OTU(DNP3StaticObject[ElementIndex].RemoteForced) ];
   11: XIC(EntryValidForProcessing)[XIC(EventBuffer[UnloadIndex].EvtFlags.4) OTL(DNP3StaticObject[ElementIndex].LocalForced) ,XIO(EventBuffer[UnloadIndex].EvtFlags.4) OTU(DNP3StaticObject[ElementIndex].LocalForced) ];
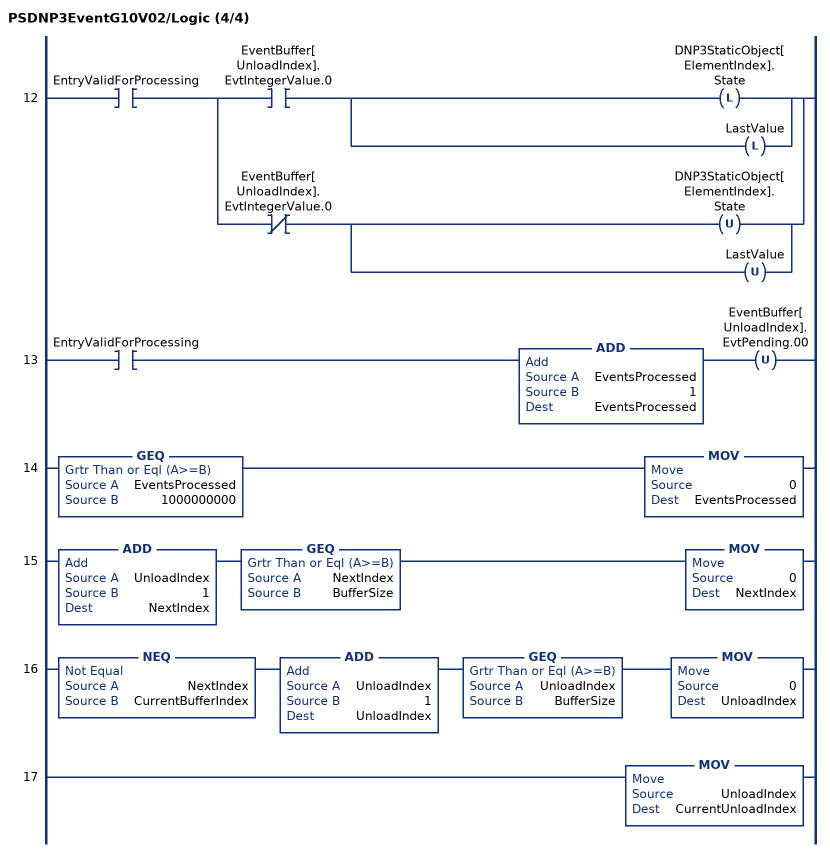
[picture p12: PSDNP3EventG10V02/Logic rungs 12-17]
   12: XIC(EntryValidForProcessing)[XIC(EventBuffer[UnloadIndex].EvtIntegerValue.0) [OTL(DNP3StaticObject[ElementIndex].State) ,OTL(LastValue) ] ,XIO(EventBuffer[UnloadIndex].EvtIntegerValue.0) [OTU(DNP3StaticObject[ElementIndex].State) ,OTU(LastValue) ] ];
   13: XIC(EntryValidForProcessing)ADD(EventsProcessed,1,EventsProcessed)OTU(EventBuffer[UnloadIndex].EvtPending.00);
   14: GEQ(EventsProcessed,1000000000)MOV(0,EventsProcessed);
   15: ADD(UnloadIndex,1,NextIndex)GEQ(NextIndex,BufferSize)MOV(0,NextIndex);
   16: NEQ(NextIndex,CurrentBufferIndex)ADD(UnloadIndex,1,UnloadIndex)GEQ(UnloadIndex,BufferSize)MOV(0,UnloadIndex);
   17: MOV(UnloadIndex,CurrentUnloadIndex);
END_ROUTINE
END_ADD_ON_INSTRUCTION

ADD_ON_INSTRUCTION PSDNP3EventG20V01   (* revision 1.0, vendor ProSoft Technology Inc *)
VAR_IN_OUT
   EventBuffer : PSDNP3MasterEvent[1]; {required}
END_VAR
VAR_INPUT
   BufferSize : DINT; {required}
   CurrentBufferIndex : DINT; {required}
   Reset : BOOL; {required}
   OutstationNodeAddress : INT; {required}
   OutstationIPAddress0 : INT; {required}
   OutstationIPAddress1 : INT; {required}
   OutstationIPAddress2 : INT; {required}
   OutstationIPAddress3 : INT; {required}
END_VAR
VAR_IN_OUT
   DNP3StaticObject : PSDNP3Counter32WithFlag[1]; {required}
END_VAR
VAR_INPUT
   MaxtElementCount : DINT; {required}
END_VAR
VAR_OUTPUT
   EventsProcessed : DINT; {access Read Only, visible}
   LastElementIndex : DINT; {access Read Only, visible}
   LastValue : DINT; {access Read Only, visible}
   LastStatus : SINT; {access Read Only, visible}
   CurrentUnloadIndex : DINT; {access Read Only, visible}
END_VAR
VAR
   UnloadIndex : DINT; {access None}
   EnableInTemp : BOOL; {access None}
   InitialScan : BOOL; {access None}
   EntryValidForProcessing : BOOL; {access None}
   ElementIndex : DINT; {access None}
   NextIndex : DINT; {access None}
   ResetPulse : BOOL; {access None}
   ResetONS : BOOL; {access None}
END_VAR

ROUTINE Logic   (* ladder *)
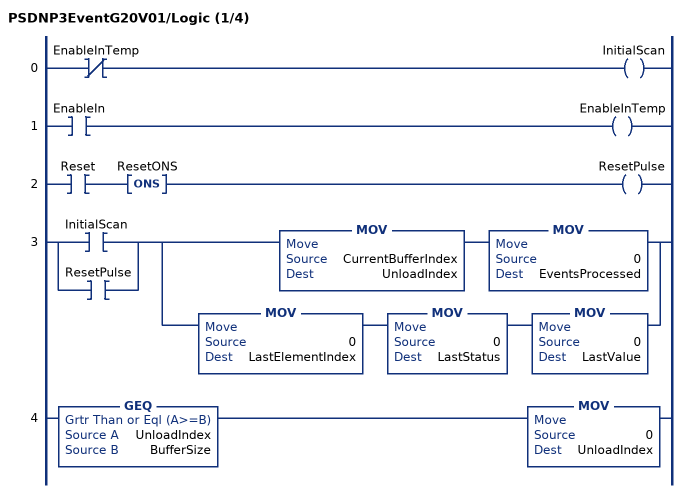
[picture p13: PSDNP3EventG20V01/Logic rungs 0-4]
   0: XIO(EnableInTemp)OTE(InitialScan);
   1: XIC(EnableIn)OTE(EnableInTemp);
   2: XIC(Reset)ONS(ResetONS)OTE(ResetPulse);
   3: [XIC(InitialScan) ,XIC(ResetPulse) ][MOV(CurrentBufferIndex,UnloadIndex) MOV(0,EventsProcessed) ,MOV(0,LastElementIndex) MOV(0,LastStatus) MOV(0,LastValue) ];
   4: GEQ(UnloadIndex,BufferSize)MOV(0,UnloadIndex);
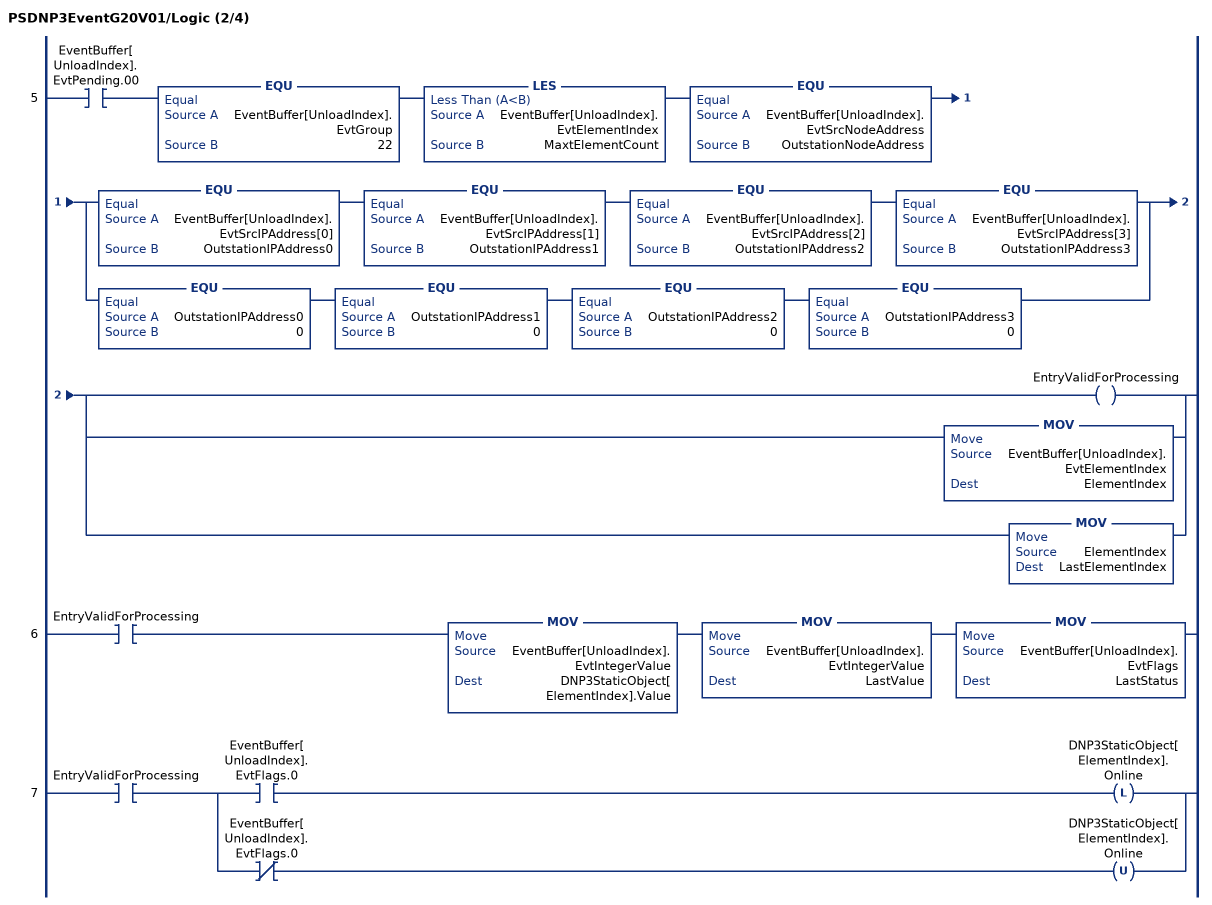
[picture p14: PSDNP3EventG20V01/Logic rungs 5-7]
   5: XIC(EventBuffer[UnloadIndex].EvtPending.00)EQU(EventBuffer[UnloadIndex].EvtGroup,22)LES(EventBuffer[UnloadIndex].EvtElementIndex,MaxtElementCount)EQU(EventBuffer[UnloadIndex].EvtSrcNodeAddress,OutstationNodeAddress)[EQU(EventBuffer[UnloadIndex].EvtSrcIPAddress[0],OutstationIPAddress0) EQU(EventBuffer[UnloadIndex].EvtSrcIPAddress[1],OutstationIPAddress1) EQU(EventBuffer[UnloadIndex].EvtSrcIPAddress[2],OutstationIPAddress2) EQU(EventBuffer[UnloadIndex].EvtSrcIPAddress[3],OutstationIPAddress3) ,EQU(OutstationIPAddress0,0) EQU(OutstationIPAddress1,0) EQU(OutstationIPAddress2,0) EQU(OutstationIPAddress3,0) ][OTE(EntryValidForProcessing) ,MOV(EventBuffer[UnloadIndex].EvtElementIndex,ElementIndex) ,MOV(ElementIndex,LastElementIndex) ];
   6: XIC(EntryValidForProcessing)MOV(EventBuffer[UnloadIndex].EvtIntegerValue,DNP3StaticObject[ElementIndex].Value)MOV(EventBuffer[UnloadIndex].EvtIntegerValue,LastValue)MOV(EventBuffer[UnloadIndex].EvtFlags,LastStatus);
   7: XIC(EntryValidForProcessing)[XIC(EventBuffer[UnloadIndex].EvtFlags.0) OTL(DNP3StaticObject[ElementIndex].Online) ,XIO(EventBuffer[UnloadIndex].EvtFlags.0) OTU(DNP3StaticObject[ElementIndex].Online) ];
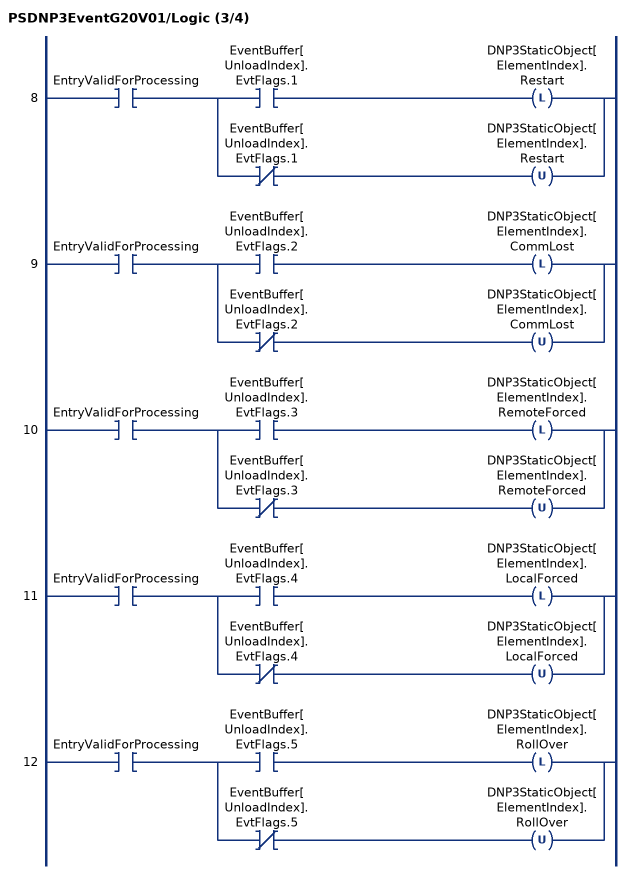
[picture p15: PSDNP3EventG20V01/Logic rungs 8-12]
   8: XIC(EntryValidForProcessing)[XIC(EventBuffer[UnloadIndex].EvtFlags.1) OTL(DNP3StaticObject[ElementIndex].Restart) ,XIO(EventBuffer[UnloadIndex].EvtFlags.1) OTU(DNP3StaticObject[ElementIndex].Restart) ];
   9: XIC(EntryValidForProcessing)[XIC(EventBuffer[UnloadIndex].EvtFlags.2) OTL(DNP3StaticObject[ElementIndex].CommLost) ,XIO(EventBuffer[UnloadIndex].EvtFlags.2) OTU(DNP3StaticObject[ElementIndex].CommLost) ];
   10: XIC(EntryValidForProcessing)[XIC(EventBuffer[UnloadIndex].EvtFlags.3) OTL(DNP3StaticObject[ElementIndex].RemoteForced) ,XIO(EventBuffer[UnloadIndex].EvtFlags.3) OTU(DNP3StaticObject[ElementIndex].RemoteForced) ];
   11: XIC(EntryValidForProcessing)[XIC(EventBuffer[UnloadIndex].EvtFlags.4) OTL(DNP3StaticObject[ElementIndex].LocalForced) ,XIO(EventBuffer[UnloadIndex].EvtFlags.4) OTU(DNP3StaticObject[ElementIndex].LocalForced) ];
   12: XIC(EntryValidForProcessing)[XIC(EventBuffer[UnloadIndex].EvtFlags.5) OTL(DNP3StaticObject[ElementIndex].RollOver) ,XIO(EventBuffer[UnloadIndex].EvtFlags.5) OTU(DNP3StaticObject[ElementIndex].RollOver) ];
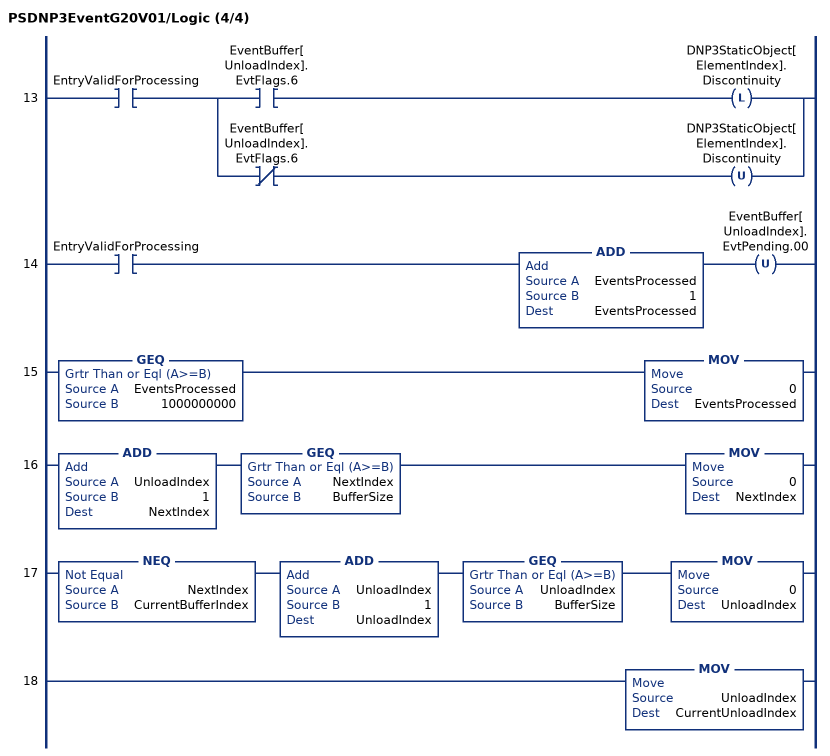
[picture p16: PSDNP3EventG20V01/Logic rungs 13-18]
   13: XIC(EntryValidForProcessing)[XIC(EventBuffer[UnloadIndex].EvtFlags.6) OTL(DNP3StaticObject[ElementIndex].Discontinuity) ,XIO(EventBuffer[UnloadIndex].EvtFlags.6) OTU(DNP3StaticObject[ElementIndex].Discontinuity) ];
   14: XIC(EntryValidForProcessing)ADD(EventsProcessed,1,EventsProcessed)OTU(EventBuffer[UnloadIndex].EvtPending.00);
   15: GEQ(EventsProcessed,1000000000)MOV(0,EventsProcessed);
   16: ADD(UnloadIndex,1,NextIndex)GEQ(NextIndex,BufferSize)MOV(0,NextIndex);
   17: NEQ(NextIndex,CurrentBufferIndex)ADD(UnloadIndex,1,UnloadIndex)GEQ(UnloadIndex,BufferSize)MOV(0,UnloadIndex);
   18: MOV(UnloadIndex,CurrentUnloadIndex);
END_ROUTINE
END_ADD_ON_INSTRUCTION

ADD_ON_INSTRUCTION PSDNP3EventG20V02   (* revision 1.0, vendor ProSoft Technology Inc *)
VAR_IN_OUT
   EventBuffer : PSDNP3MasterEvent[1]; {required}
END_VAR
VAR_INPUT
   BufferSize : DINT; {required}
   CurrentBufferIndex : DINT; {required}
   Reset : BOOL; {required}
   OutstationNodeAddress : INT; {required}
   OutstationIPAddress0 : INT; {required}
   OutstationIPAddress1 : INT; {required}
   OutstationIPAddress2 : INT; {required}
   OutstationIPAddress3 : INT; {required}
END_VAR
VAR_IN_OUT
   DNP3StaticObject : PSDNP3Counter16WithFlag[1]; {required}
END_VAR
VAR_INPUT
   MaxtElementCount : DINT; {required}
END_VAR
VAR_OUTPUT
   EventsProcessed : DINT; {access Read Only, visible}
   LastElementIndex : DINT; {access Read Only, visible}
   LastValue : DINT; {access Read Only, visible}
   LastStatus : SINT; {access Read Only, visible}
   CurrentUnloadIndex : DINT; {access Read Only, visible}
END_VAR
VAR
   UnloadIndex : DINT; {access None}
   EnableInTemp : BOOL; {access None}
   InitialScan : BOOL; {access None}
   EntryValidForProcessing : BOOL; {access None}
   ElementIndex : DINT; {access None}
   NextIndex : DINT; {access None}
   ResetPulse : BOOL; {access None}
   ResetONS : BOOL; {access None}
END_VAR

ROUTINE Logic   (* ladder *)
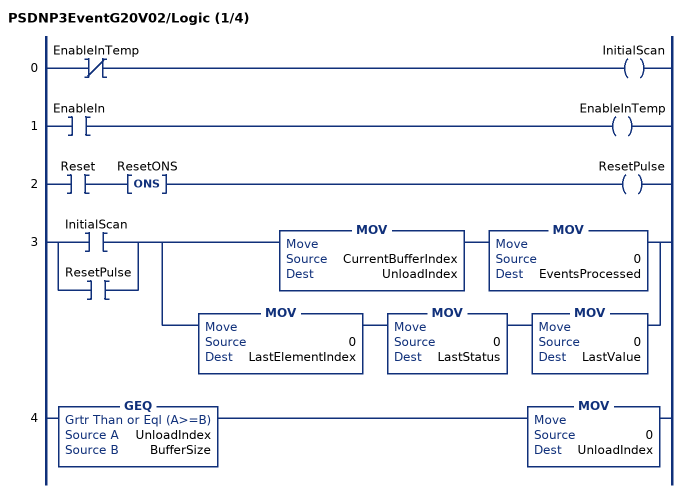
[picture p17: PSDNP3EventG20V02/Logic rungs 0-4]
   0: XIO(EnableInTemp)OTE(InitialScan);
   1: XIC(EnableIn)OTE(EnableInTemp);
   2: XIC(Reset)ONS(ResetONS)OTE(ResetPulse);
   3: [XIC(InitialScan) ,XIC(ResetPulse) ][MOV(CurrentBufferIndex,UnloadIndex) MOV(0,EventsProcessed) ,MOV(0,LastElementIndex) MOV(0,LastStatus) MOV(0,LastValue) ];
   4: GEQ(UnloadIndex,BufferSize)MOV(0,UnloadIndex);
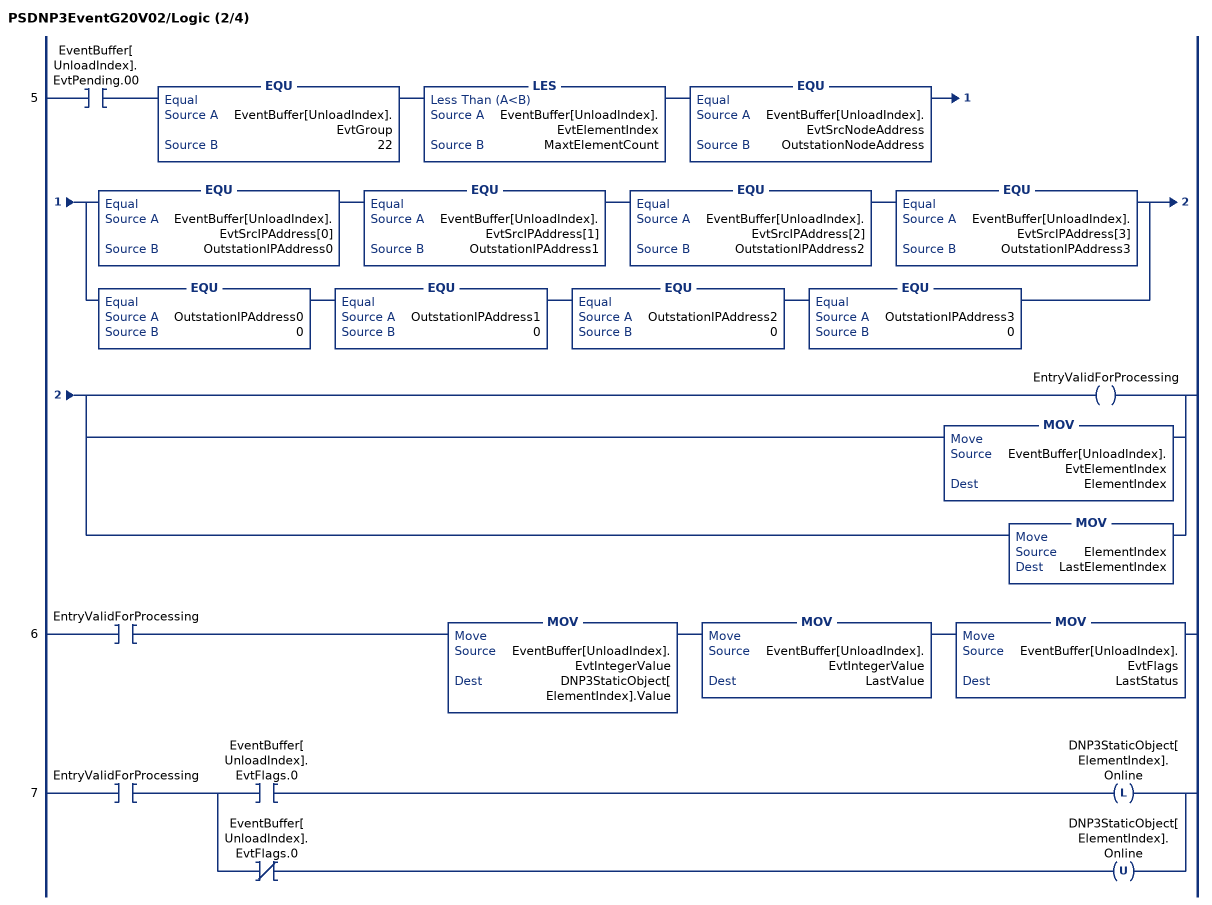
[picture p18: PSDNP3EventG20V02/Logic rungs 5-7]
   5: XIC(EventBuffer[UnloadIndex].EvtPending.00)EQU(EventBuffer[UnloadIndex].EvtGroup,22)LES(EventBuffer[UnloadIndex].EvtElementIndex,MaxtElementCount)EQU(EventBuffer[UnloadIndex].EvtSrcNodeAddress,OutstationNodeAddress)[EQU(EventBuffer[UnloadIndex].EvtSrcIPAddress[0],OutstationIPAddress0) EQU(EventBuffer[UnloadIndex].EvtSrcIPAddress[1],OutstationIPAddress1) EQU(EventBuffer[UnloadIndex].EvtSrcIPAddress[2],OutstationIPAddress2) EQU(EventBuffer[UnloadIndex].EvtSrcIPAddress[3],OutstationIPAddress3) ,EQU(OutstationIPAddress0,0) EQU(OutstationIPAddress1,0) EQU(OutstationIPAddress2,0) EQU(OutstationIPAddress3,0) ][OTE(EntryValidForProcessing) ,MOV(EventBuffer[UnloadIndex].EvtElementIndex,ElementIndex) ,MOV(ElementIndex,LastElementIndex) ];
   6: XIC(EntryValidForProcessing)MOV(EventBuffer[UnloadIndex].EvtIntegerValue,DNP3StaticObject[ElementIndex].Value)MOV(EventBuffer[UnloadIndex].EvtIntegerValue,LastValue)MOV(EventBuffer[UnloadIndex].EvtFlags,LastStatus);
   7: XIC(EntryValidForProcessing)[XIC(EventBuffer[UnloadIndex].EvtFlags.0) OTL(DNP3StaticObject[ElementIndex].Online) ,XIO(EventBuffer[UnloadIndex].EvtFlags.0) OTU(DNP3StaticObject[ElementIndex].Online) ];
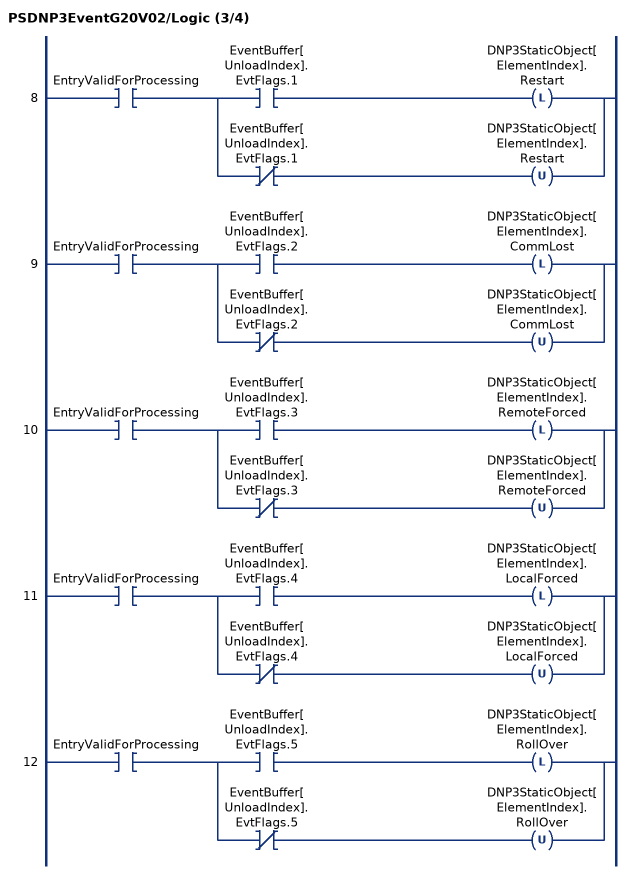
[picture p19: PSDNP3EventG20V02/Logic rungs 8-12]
   8: XIC(EntryValidForProcessing)[XIC(EventBuffer[UnloadIndex].EvtFlags.1) OTL(DNP3StaticObject[ElementIndex].Restart) ,XIO(EventBuffer[UnloadIndex].EvtFlags.1) OTU(DNP3StaticObject[ElementIndex].Restart) ];
   9: XIC(EntryValidForProcessing)[XIC(EventBuffer[UnloadIndex].EvtFlags.2) OTL(DNP3StaticObject[ElementIndex].CommLost) ,XIO(EventBuffer[UnloadIndex].EvtFlags.2) OTU(DNP3StaticObject[ElementIndex].CommLost) ];
   10: XIC(EntryValidForProcessing)[XIC(EventBuffer[UnloadIndex].EvtFlags.3) OTL(DNP3StaticObject[ElementIndex].RemoteForced) ,XIO(EventBuffer[UnloadIndex].EvtFlags.3) OTU(DNP3StaticObject[ElementIndex].RemoteForced) ];
   11: XIC(EntryValidForProcessing)[XIC(EventBuffer[UnloadIndex].EvtFlags.4) OTL(DNP3StaticObject[ElementIndex].LocalForced) ,XIO(EventBuffer[UnloadIndex].EvtFlags.4) OTU(DNP3StaticObject[ElementIndex].LocalForced) ];
   12: XIC(EntryValidForProcessing)[XIC(EventBuffer[UnloadIndex].EvtFlags.5) OTL(DNP3StaticObject[ElementIndex].RollOver) ,XIO(EventBuffer[UnloadIndex].EvtFlags.5) OTU(DNP3StaticObject[ElementIndex].RollOver) ];
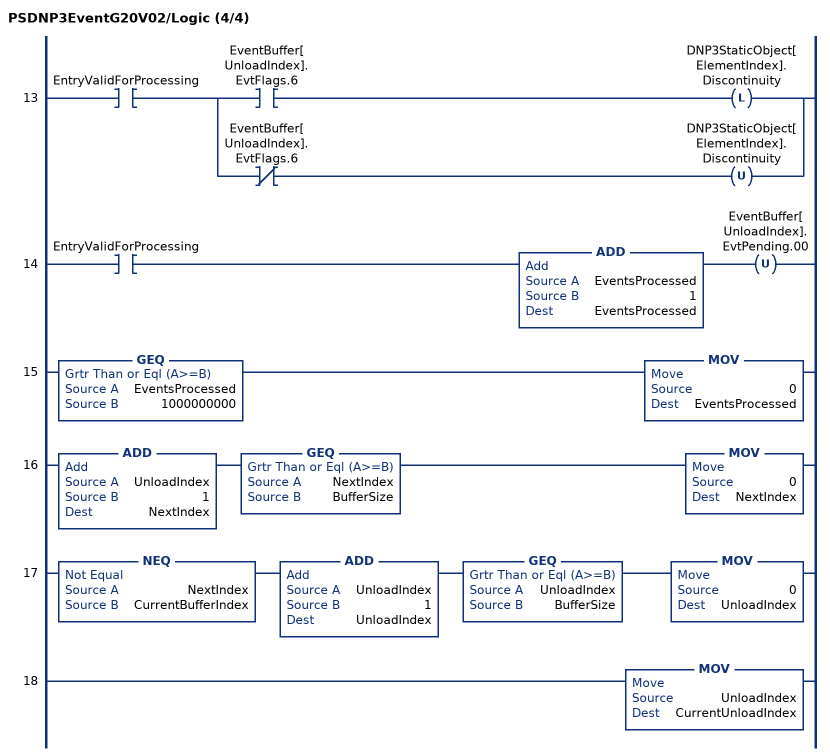
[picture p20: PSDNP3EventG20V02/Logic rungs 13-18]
   13: XIC(EntryValidForProcessing)[XIC(EventBuffer[UnloadIndex].EvtFlags.6) OTL(DNP3StaticObject[ElementIndex].Discontinuity) ,XIO(EventBuffer[UnloadIndex].EvtFlags.6) OTU(DNP3StaticObject[ElementIndex].Discontinuity) ];
   14: XIC(EntryValidForProcessing)ADD(EventsProcessed,1,EventsProcessed)OTU(EventBuffer[UnloadIndex].EvtPending.00);
   15: GEQ(EventsProcessed,1000000000)MOV(0,EventsProcessed);
   16: ADD(UnloadIndex,1,NextIndex)GEQ(NextIndex,BufferSize)MOV(0,NextIndex);
   17: NEQ(NextIndex,CurrentBufferIndex)ADD(UnloadIndex,1,UnloadIndex)GEQ(UnloadIndex,BufferSize)MOV(0,UnloadIndex);
   18: MOV(UnloadIndex,CurrentUnloadIndex);
END_ROUTINE
END_ADD_ON_INSTRUCTION
